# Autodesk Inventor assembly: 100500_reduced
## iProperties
Created: 2007-12
Part Number: 100500_reduced
Document SubType Name: Assembly
Designer: MM
Mass: 67948.6 g
Surface Area: 51487.2 cm^2
Volume: 67429.6 cm^3
Density: 1.0077 g/cm^3
Description: SUPER CAR DRIVER SEAT 1000
Component Category: Seat Assembly
Author: MM
